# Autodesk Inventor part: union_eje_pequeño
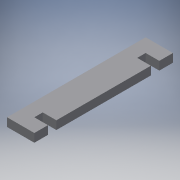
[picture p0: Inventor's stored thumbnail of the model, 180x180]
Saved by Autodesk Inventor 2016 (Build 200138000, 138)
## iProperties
Created: 2017-06
Part Number: union_eje_pequeño
Material: Generic
Document SubType Name: Modeling
Designer: laboratorioesan
Density: 1 g/cm^3
Appearance: Default
Author: laboratorioesan
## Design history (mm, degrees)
sketch "Sketch1"
  geometry: L1 (0, 226.5)-(30, 226.5) reference; L2 (0, 208)-(0, 226.5) reference; L3 (30, 208)-(0, 208) reference; L4 (30, 226.5)-(30, 208) reference; L5 (0, 0)-(30, 0) reference; L6 (0, -18.5)-(0, 0) reference; L7 (30, -18.5)-(0, -18.5) reference; L8 (30, 0)-(30, -18.5) reference; L9 (30, 226.5)-(0, 226.5); L10 (0, 226.5)-(0, 208); L11 (0, 208)-(30, 208); L12 (30, 208)-(30, 226.5); L13 (0, -18.5)-(30, -18.5); L14 (30, -18.5)-(30, 0); L15 (30, 0)-(0, 0); L16 (0, 0)-(0, -18.5); L17 (0, 226.5)-(60, 226.5); L18 (60, 226.5)-(60, 256.5); L19 (60, 256.5)-(0, 256.5); L20 (0, 256.5)-(0, 226.5); L21 (0, -18.5)-(60, -18.5); L22 (60, -18.5)-(60, -48.5); L23 (60, -48.5)-(0, -48.5); L24 (0, -48.5)-(0, -18.5); L25 (0, 208)-(60, 208); L26 (60, 208)-(60, 0); L27 (60, 0)-(0, 0); L28 (0, 0)-(0, 208)
  constraints: 40 end point, 10 parallel, 5 horizontal, 5 perpendicular, 1 point on line
  dimensions: "d0" = 60 distance of L19.end L18.end; "d1" = 30 distance of L18.end L17.end; "d2" = 60 distance of L22.end L23.end; "d3" = 30 distance of L21.end L22.end
extrude "Extrusion1" new body sketch "Sketch1" distance "d4" = 18.5; taper "d5" = 0 deg
body "Solid1"
node "Reference1"
node "Reference2"
